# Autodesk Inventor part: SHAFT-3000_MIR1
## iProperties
Created: 2007-08
Part Number: SHAFT-3000_MIR1
Material: Stainless Steel
Document SubType Name: Modeling
Density: 8.08 g/cm^3
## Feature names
1. Derived Body1 [Tagging]
